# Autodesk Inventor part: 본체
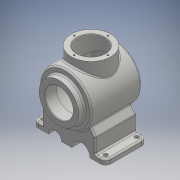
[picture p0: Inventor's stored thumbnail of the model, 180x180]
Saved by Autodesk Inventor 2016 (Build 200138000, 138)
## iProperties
Created: 2018-08
Part Number: 본체
Material: 일반
Document SubType Name: Modeling
Designer: USER
Density: 1 g/cm^3
Appearance: 기본값
Author: USER
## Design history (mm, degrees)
sketch "스케치1"
  geometry: C1 r 38 at (0, 0); 1 further point
  constraints: 1 centre point, 1 coincident
  dimensions: "d0" = 76 diameter of C1
extrude "돌출1" new body sketch "스케치1" distance "d1" = 12; taper "d2" = 0 deg
sketch "스케치2"
  geometry: L1 (0, 38)-(0, -38) reference; L2 (0, 0)-(-43.367, 0); L3 (12, 50)-(108.671, 50); L4 (120, 0)-(120, 54.462); L5 (120, 0)-(12, 0); L6 (12, 0)-(12, 39); L7 (12, 50)-(12, 0); A1 r 116 centre (4, 0) between (120, 0) and (108.671, 50); 4 further points; 1 other entity
  constraints: 12 end point, 7 horizontal alignment, 2 horizontal, 2 midpoint, 2 point on circle, 2 vertical alignment, 1 centre point, 1 perpendicular, 1 vertical, 1 other
  dimensions: "d6" = 100 diameter of L3 L2; "d9" = 116 radius of A1; "d10" = 108 distance between parallel lines of L4 L7
revolve "회전1" sketch "스케치2" stored, may be unused: angle "d11" = 90 deg
node "작업 평면1"
sketch "스케치3"
  geometry: L1 (-70, 20)-(70, 20); L2 (70, 20)-(70, 100); L3 (70, 100)-(-70, 100); L4 (-70, 100)-(-70, 20); L5 (50, 12)-(-50, 12) reference; 2 further points
  constraints: 8 end point, 2 parallel, 1 horizontal, 1 midpoint, 1 perpendicular, 1 vertical alignment
  dimensions: "d13" = 140 distance of L1.start L1.end; "d14" = 80 distance of L3.end L1.start; "d15" = 8 distance between parallel lines of L1 L5
extrude "돌출2" join sketch "스케치3" distance "d16" = 10; taper "d17" = 0 deg
node "작업 평면2"
sketch "스케치4"
  geometry: L1 (140, 0)-(0, 0); L2 (0, 0)-(0, 10); L3 (70, 10)-(20, 10); L4 (140, 0)-(140, 10); L5 (140, 10)-(0, 10) reference; L6 (20, 10)-(20, 38.563); L7 (20, 38.563)-(29.696, 52.41); L8 (20, 10)-(70, 10); L9 (20, 38.563)-(0, 10); L10 (70, 10)-(70, 32); A1 r 50 centre (70, 82) between (29.696, 52.41) and (70, 32) reference; 1 further point
  constraints: 12 end point, 2 point on circle, 1 collinear, 1 perpendicular, 1 point on line, 1 vertical
  dimensions: "d24" = 20 horizontal distance of L2.end L6.end; "d25" = 35 deg angle of L2 L9; "d27" = 29.69578 horizontal distance of L2.end L7.end; "d28" = 22 distance of L3.start L10.end
feature "리브1" sketch "스케치4" dims "d29" = 1, "d30" = 80, "d31" = 0, "d32" = 0, "d33" = 1, "d34" = 1
node "작업 평면3"
sketch "스케치6"
  geometry: L1 (140, 0)-(140, 10) reference; L2 (140, 10)-(70, 10) reference; L3 (120, 10)-(120, 38.563); L4 (120, 38.563)-(110.304, 52.41); 2 further points
  constraints: 4 end point, 1 point on line, 1 vertical, 2 other
  dimensions: "d54" = 20 distance between parallel lines of L1 L3; "d56" = 35 deg angle of L1 L4; "d57" = 29.69578 horizontal distance of L1.end L4.end
feature "리브3" sketch "스케치6" dims "d58" = 1, "d59" = 80, "d60" = 0, "d61" = 0, "d62" = 1, "d63" = 1
sketch "스케치7"
  geometry: C1 r 27 at (0, 0); 1 further point
  constraints: 1 centre point, 1 coincident
  dimensions: "d64" = 54 diameter of C1
extrude "돌출3" cut sketch "스케치7" distance "d65" = 22; taper "d66" = 0 deg
sketch "스케치8"
  geometry: L1 (0, 0)-(-23.539, 0); L2 (22, 40)-(102.163, 40); L3 (22, 40)-(22, 0); L4 (22, -27)-(22, 27) reference; L5 (108.671, -50)-(108.671, 50) reference; L6 (22, 0)-(110, 0); A1 r 116 centre (4, 0) between (108.671, -50) and (108.671, 50) reference; A2 r 106 centre (4, 0) between (110, 0) and (102.163, 40)
  constraints: 8 end point, 2 horizontal, 2 point on circle, 1 centre point, 1 midpoint, 1 perpendicular
  dimensions: "d68" = 80 diameter of L2 L1; "d69" = 40 distance of L2.start L3.end; "d70" = 10 radial gap between concentric circles of A2 A1
revolve "회전2" sketch "스케치8" stored, may be unused: angle "d71" = 90 deg
node "작업 평면4"
sketch "스케치9"
  geometry: L1 (50, 12)-(-50, 12) reference; C1 r 38 at (0, 62); 2 further points
  constraints: 1 centre point, 1 midpoint, 1 vertical alignment
  dimensions: "d73" = 76 diameter of C1; "d74" = 50 distance from line of L1 C1.centre
extrude "돌출4" join sketch "스케치9" stored distance "d75" = 22; taper "d76" = 0 deg
sketch "스케치10"
  geometry: C1 r 38 at (0, 0) reference; C2 r 27 at (0, 0); 1 further point
  constraints: 1 centre point, 1 coincident
  dimensions: "d77" = 54 diameter of C2
extrude "돌출5" cut sketch "스케치10" distance "d78" = 50; taper "d79" = 0 deg
sketch "스케치11"
  geometry: C1 r 38 at (0, 0) reference; 2 further points
  constraints: 1 vertical alignment
  dimensions: "d80" = 32.5 distance of C1.centre point (0, 32.5)
hole "구멍1" sketch "스케치11" at (0, 32.5) diameter "d81" = 3.242; stored, may be unused: countersink angle "d85" = 90 deg, drill point angle "d87" = 118 deg; dims "d82" = 8, "d83" = 4, "d84" = 2, "d86" = 10
sketch "스케치12"
  geometry: 2 further points
  constraints: 1 vertical alignment
  dimensions: "d91" = 32.5 distance of point (0, 0) point (0, 32.5)
hole "구멍2" sketch "스케치12" at (0, 32.5) diameter "d92" = 3.242; stored, may be unused: countersink angle "d96" = 90 deg, drill point angle "d98" = 118 deg; dims "d93" = 8, "d94" = 4, "d95" = 2, "d97" = 10
sketch "스케치13"
  geometry: L1 (0, 0)-(140, 0) reference; L2 (140, 0)-(0, 0) reference; L3 (70, 0)-(70, 18.218); L4 (30, 0)-(55, 0); L5 (75, 0)-(110, 0); A1 r 12.5 centre (42.5, 0) between (55, 0) and (30, 0); A2 r 17.5 centre (92.5, 0) between (110, 0) and (75, 0); 2 further points
  constraints: 6 end point, 6 point on line, 4 point on circle, 2 centre point, 2 collinear, 2 midpoint, 1 horizontal alignment, 1 vertical
  dimensions: "d102" = 27.5 distance from line of A1.centre L3; "d103" = 12.5 radius of A1; "d104" = 22.5 distance from line of A2.centre L3; "d105" = 17.5 radius of A2
extrude "돌출6" cut sketch "스케치13" stored distance "d106" = 50; taper "d107" = 0 deg
extrude "돌출7" cut sketch "스케치13" stored distance "d108" = 50; taper "d109" = 0 deg
fillet "모깎기1" dims "d110" = 10
sketch "스케치14"
  geometry: L1 (-70, 90)-(-70, 30) reference; L2 (-40, 100)-(-60, 100) reference; L3 (-40, 100)-(-40, 20) reference; L4 (-60, 20)-(-40, 20) reference; C1 r 4 at (-60, 90); A1 r 10 centre (-60, 30) between (-70, 30) and (-60, 20) reference; A2 r 10 centre (-60, 90) between (-60, 100) and (-70, 90) reference; 1 further point
  constraints: 1 centre point, 1 coincident
  dimensions: "d111" = 8 diameter of C1
extrude "돌출8" cut sketch "스케치14" stored distance "d112" = 50; taper "d113" = 0 deg
fillet "모깎기2" dims "d114" = 3
fillet "모깎기3" dims "d115" = 3
fillet "모깎기4" dims "d116" = 3
fillet "모깎기5" dims "d117" = 3
fillet "모깎기6" dims "d118" = 3
chamfer "모따기1" distance "d119" = 1; stored, may be unused: second distance "d120" = 2, angle "d121" = 45 deg
chamfer "모따기2" distance "d122" = 1; stored, may be unused: second distance "d123" = 2, angle "d124" = 45 deg
node "작업 평면5"
sketch "스케치15" dims "d6" = 100
  geometry: 2 further points
  constraints: 1 vertical alignment, 1 other
  dimensions: "d125" = 32.5 distance of point (0, 32.5) point (0, 0)
feature "엠보싱1" sketch "스케치15" dims "d126" = 0.5, "d127" = 0
fillet "모깎기7" dims "d128" = 3
fillet "모깎기8" dims "d129" = 3
fillet "모깎기9" dims "d130" = 3
fillet "모깎기10" dims "d131" = 3
fillet "모깎기11" dims "d132" = 3
fillet "모깎기12" dims "d133" = 3
node "솔리드1"
pattern_circular "원형 패턴1" dims angle "d89" = 360 deg
pattern_circular "원형 패턴2" dims angle "d100" = 360 deg
mirror "대칭1"
mirror "대칭2"
node "투영된 루프2"
node "투영된 루프3"
node "투영된 루프4"
other parameters: "d12" = -82, "d36" = 35 deg, "d55" = 35 deg, "d67" = 10, "d72" = -147
